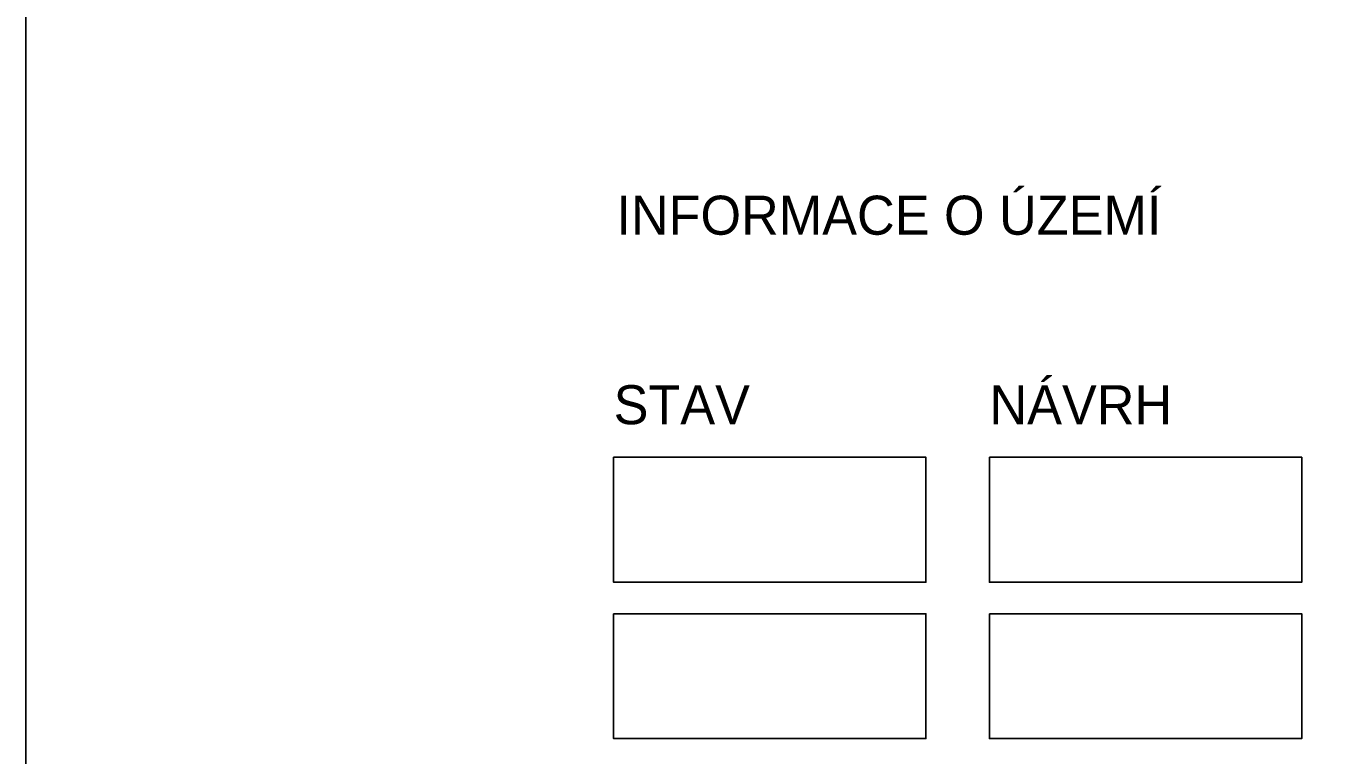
# Model space of a CAD drawing. Extents: x -449577 to -425530, y -1150048 to -1121091.
# Drawn here: x -443521.8 to -443089.1, y -1148794.2 to -1148551.4 of the extents above; entities that cross this region are included whole.
import ezdxf

# ---------------------------------------------------------------- set-up
doc = ezdxf.new("R2010")
doc.units = 0
doc.layers.add('Vrstva 1', color=7, linetype='Continuous')

msp = doc.modelspace()

# ---------------------------------------------------------------- linework, layer by layer
at = {"layer": 'Vrstva 1'}
for points in [[(-441021.77, -1148048.33), (-441021.77, -1150048.33), (-443521.77, -1150048.33), (-443521.77, -1148048.33)], [(-441021.77, -1148048.33), (-441021.77, -1150048.33), (-443521.77, -1150048.33), (-443521.77, -1148048.33)], [(-441021.77, -1148048.33), (-441021.77, -1150048.33), (-443521.77, -1150048.33), (-443521.77, -1148048.33)], [(-441021.77, -1148048.33), (-441021.77, -1150048.33), (-443521.77, -1150048.33), (-443521.77, -1148048.33)], [(-441021.77, -1148048.33), (-441021.77, -1150048.33), (-443521.77, -1150048.33), (-443521.77, -1148048.33)], [(-441021.77, -1148048.33), (-441021.77, -1150048.33), (-443521.77, -1150048.33), (-443521.77, -1148048.33)], [(-441021.77, -1148048.33), (-441021.77, -1150048.33), (-443521.77, -1150048.33), (-443521.77, -1148048.33)], [(-441021.77, -1148048.33), (-441021.77, -1150048.33), (-443521.77, -1150048.33), (-443521.77, -1148048.33)], [(-441021.77, -1148048.33), (-441021.77, -1150048.33), (-443521.77, -1150048.33), (-443521.77, -1148048.33)], [(-441021.77, -1148048.33), (-441021.77, -1150048.33), (-443521.77, -1150048.33), (-443521.77, -1148048.33)], [(-441021.77, -1148048.33), (-441021.77, -1150048.33), (-443521.77, -1150048.33), (-443521.77, -1148048.33)], [(-441021.77, -1148048.33), (-441021.77, -1150048.33), (-443521.77, -1150048.33), (-443521.77, -1148048.33)], [(-441021.77, -1148048.33), (-441021.77, -1150048.33), (-443521.77, -1150048.33), (-443521.77, -1148048.33)], [(-441021.77, -1148048.33), (-441021.77, -1150048.33), (-443521.77, -1150048.33), (-443521.77, -1148048.33)], [(-441021.77, -1148048.33), (-441021.77, -1150048.33), (-443521.77, -1150048.33), (-443521.77, -1148048.33)], [(-441021.77, -1148048.33), (-441021.77, -1150048.33), (-443521.77, -1150048.33), (-443521.77, -1148048.33)], [(-441021.77, -1148048.33), (-441021.77, -1150048.33), (-443521.77, -1150048.33), (-443521.77, -1148048.33)], [(-441021.77, -1148048.33), (-441021.77, -1150048.33), (-443521.77, -1150048.33), (-443521.77, -1148048.33)], [(-441021.77, -1148048.33), (-441021.77, -1150048.33), (-443521.77, -1150048.33), (-443521.77, -1148048.33)], [(-441021.77, -1148048.33), (-441021.77, -1150048.33), (-443521.77, -1150048.33), (-443521.77, -1148048.33)], [(-441021.77, -1148048.33), (-441021.77, -1150048.33), (-443521.77, -1150048.33), (-443521.77, -1148048.33)], [(-441021.77, -1148048.33), (-441021.77, -1150048.33), (-443521.77, -1150048.33), (-443521.77, -1148048.33)], [(-441021.77, -1148048.33), (-441021.77, -1150048.33), (-443521.77, -1150048.33), (-443521.77, -1148048.33)], [(-441021.77, -1148048.33), (-441021.77, -1150048.33), (-443521.77, -1150048.33), (-443521.77, -1148048.33)], [(-441021.77, -1148048.33), (-441021.77, -1150048.33), (-443521.77, -1150048.33), (-443521.77, -1148048.33)], [(-441021.77, -1148048.33), (-441021.77, -1150048.33), (-443521.77, -1150048.33), (-443521.77, -1148048.33)], [(-441021.77, -1148048.33), (-441021.77, -1150048.33), (-443521.77, -1150048.33), (-443521.77, -1148048.33)], [(-441021.77, -1148048.33), (-441021.77, -1150048.33), (-443521.77, -1150048.33), (-443521.77, -1148048.33)], [(-441021.77, -1148048.33), (-441021.77, -1150048.33), (-443521.77, -1150048.33), (-443521.77, -1148048.33)], [(-441021.77, -1148048.33), (-441021.77, -1150048.33), (-443521.77, -1150048.33), (-443521.77, -1148048.33)], [(-441021.77, -1148048.33), (-441021.77, -1150048.33), (-443521.77, -1150048.33), (-443521.77, -1148048.33)], [(-441021.77, -1148048.33), (-441021.77, -1150048.33), (-443521.77, -1150048.33), (-443521.77, -1148048.33)], [(-443326.02, -1148695.02), (-443222.02, -1148695.02), (-443222.02, -1148736.62), (-443326.02, -1148736.62)], [(-443326.02, -1148695.02), (-443222.02, -1148695.02), (-443222.02, -1148736.62), (-443326.02, -1148736.62)], [(-443326.02, -1148695.02), (-443222.02, -1148695.02), (-443222.02, -1148736.62), (-443326.02, -1148736.62)], [(-443326.02, -1148695.02), (-443222.02, -1148695.02), (-443222.02, -1148736.62), (-443326.02, -1148736.62)], [(-443326.02, -1148695.02), (-443222.02, -1148695.02), (-443222.02, -1148736.62), (-443326.02, -1148736.62)], [(-443326.02, -1148695.02), (-443222.02, -1148695.02), (-443222.02, -1148736.62), (-443326.02, -1148736.62)], [(-443326.02, -1148695.02), (-443222.02, -1148695.02), (-443222.02, -1148736.62), (-443326.02, -1148736.62)], [(-443326.02, -1148695.02), (-443222.02, -1148695.02), (-443222.02, -1148736.62), (-443326.02, -1148736.62)], [(-443326.02, -1148695.02), (-443222.02, -1148695.02), (-443222.02, -1148736.62), (-443326.02, -1148736.62)], [(-443326.02, -1148695.02), (-443222.02, -1148695.02), (-443222.02, -1148736.62), (-443326.02, -1148736.62)], [(-443326.02, -1148695.02), (-443222.02, -1148695.02), (-443222.02, -1148736.62), (-443326.02, -1148736.62)], [(-443326.02, -1148695.02), (-443222.02, -1148695.02), (-443222.02, -1148736.62), (-443326.02, -1148736.62)], [(-443326.02, -1148695.02), (-443222.02, -1148695.02), (-443222.02, -1148736.62), (-443326.02, -1148736.62)], [(-443326.02, -1148695.02), (-443222.02, -1148695.02), (-443222.02, -1148736.62), (-443326.02, -1148736.62)], [(-443326.02, -1148695.02), (-443222.02, -1148695.02), (-443222.02, -1148736.62), (-443326.02, -1148736.62)], [(-443326.02, -1148695.02), (-443222.02, -1148695.02), (-443222.02, -1148736.62), (-443326.02, -1148736.62)], [(-443326.02, -1148695.02), (-443222.02, -1148695.02), (-443222.02, -1148736.62), (-443326.02, -1148736.62)], [(-443326.02, -1148695.02), (-443222.02, -1148695.02), (-443222.02, -1148736.62), (-443326.02, -1148736.62)], [(-443326.02, -1148695.02), (-443222.02, -1148695.02), (-443222.02, -1148736.62), (-443326.02, -1148736.62)], [(-443326.02, -1148695.02), (-443222.02, -1148695.02), (-443222.02, -1148736.62), (-443326.02, -1148736.62)], [(-443326.02, -1148695.02), (-443222.02, -1148695.02), (-443222.02, -1148736.62), (-443326.02, -1148736.62)], [(-443326.02, -1148695.02), (-443222.02, -1148695.02), (-443222.02, -1148736.62), (-443326.02, -1148736.62)], [(-443326.02, -1148695.02), (-443222.02, -1148695.02), (-443222.02, -1148736.62), (-443326.02, -1148736.62)], [(-443326.02, -1148695.02), (-443222.02, -1148695.02), (-443222.02, -1148736.62), (-443326.02, -1148736.62)], [(-443326.02, -1148695.02), (-443222.02, -1148695.02), (-443222.02, -1148736.62), (-443326.02, -1148736.62)], [(-443326.02, -1148695.02), (-443222.02, -1148695.02), (-443222.02, -1148736.62), (-443326.02, -1148736.62)], [(-443326.02, -1148695.02), (-443222.02, -1148695.02), (-443222.02, -1148736.62), (-443326.02, -1148736.62)], [(-443326.02, -1148695.02), (-443222.02, -1148695.02), (-443222.02, -1148736.62), (-443326.02, -1148736.62)], [(-443326.02, -1148695.02), (-443222.02, -1148695.02), (-443222.02, -1148736.62), (-443326.02, -1148736.62)], [(-443326.02, -1148695.02), (-443222.02, -1148695.02), (-443222.02, -1148736.62), (-443326.02, -1148736.62)], [(-443326.02, -1148695.02), (-443222.02, -1148695.02), (-443222.02, -1148736.62), (-443326.02, -1148736.62)], [(-443326.02, -1148695.02), (-443222.02, -1148695.02), (-443222.02, -1148736.62), (-443326.02, -1148736.62)], [(-443200.82, -1148695.02), (-443096.82, -1148695.02), (-443096.82, -1148736.62), (-443200.82, -1148736.62)], [(-443200.82, -1148695.02), (-443096.82, -1148695.02), (-443096.82, -1148736.62), (-443200.82, -1148736.62)], [(-443200.82, -1148695.02), (-443096.82, -1148695.02), (-443096.82, -1148736.62), (-443200.82, -1148736.62)], [(-443200.82, -1148695.02), (-443096.82, -1148695.02), (-443096.82, -1148736.62), (-443200.82, -1148736.62)], [(-443200.82, -1148695.02), (-443096.82, -1148695.02), (-443096.82, -1148736.62), (-443200.82, -1148736.62)], [(-443200.82, -1148695.02), (-443096.82, -1148695.02), (-443096.82, -1148736.62), (-443200.82, -1148736.62)], [(-443200.82, -1148695.02), (-443096.82, -1148695.02), (-443096.82, -1148736.62), (-443200.82, -1148736.62)], [(-443200.82, -1148695.02), (-443096.82, -1148695.02), (-443096.82, -1148736.62), (-443200.82, -1148736.62)], [(-443200.82, -1148695.02), (-443096.82, -1148695.02), (-443096.82, -1148736.62), (-443200.82, -1148736.62)], [(-443200.82, -1148695.02), (-443096.82, -1148695.02), (-443096.82, -1148736.62), (-443200.82, -1148736.62)], [(-443200.82, -1148695.02), (-443096.82, -1148695.02), (-443096.82, -1148736.62), (-443200.82, -1148736.62)], [(-443200.82, -1148695.02), (-443096.82, -1148695.02), (-443096.82, -1148736.62), (-443200.82, -1148736.62)], [(-443200.82, -1148695.02), (-443096.82, -1148695.02), (-443096.82, -1148736.62), (-443200.82, -1148736.62)], [(-443200.82, -1148695.02), (-443096.82, -1148695.02), (-443096.82, -1148736.62), (-443200.82, -1148736.62)], [(-443200.82, -1148695.02), (-443096.82, -1148695.02), (-443096.82, -1148736.62), (-443200.82, -1148736.62)], [(-443200.82, -1148695.02), (-443096.82, -1148695.02), (-443096.82, -1148736.62), (-443200.82, -1148736.62)], [(-443200.82, -1148695.02), (-443096.82, -1148695.02), (-443096.82, -1148736.62), (-443200.82, -1148736.62)], [(-443200.82, -1148695.02), (-443096.82, -1148695.02), (-443096.82, -1148736.62), (-443200.82, -1148736.62)], [(-443200.82, -1148695.02), (-443096.82, -1148695.02), (-443096.82, -1148736.62), (-443200.82, -1148736.62)], [(-443200.82, -1148695.02), (-443096.82, -1148695.02), (-443096.82, -1148736.62), (-443200.82, -1148736.62)], [(-443200.82, -1148695.02), (-443096.82, -1148695.02), (-443096.82, -1148736.62), (-443200.82, -1148736.62)], [(-443200.82, -1148695.02), (-443096.82, -1148695.02), (-443096.82, -1148736.62), (-443200.82, -1148736.62)], [(-443200.82, -1148695.02), (-443096.82, -1148695.02), (-443096.82, -1148736.62), (-443200.82, -1148736.62)], [(-443200.82, -1148695.02), (-443096.82, -1148695.02), (-443096.82, -1148736.62), (-443200.82, -1148736.62)], [(-443200.82, -1148695.02), (-443096.82, -1148695.02), (-443096.82, -1148736.62), (-443200.82, -1148736.62)], [(-443200.82, -1148695.02), (-443096.82, -1148695.02), (-443096.82, -1148736.62), (-443200.82, -1148736.62)], [(-443200.82, -1148695.02), (-443096.82, -1148695.02), (-443096.82, -1148736.62), (-443200.82, -1148736.62)], [(-443200.82, -1148695.02), (-443096.82, -1148695.02), (-443096.82, -1148736.62), (-443200.82, -1148736.62)], [(-443200.82, -1148695.02), (-443096.82, -1148695.02), (-443096.82, -1148736.62), (-443200.82, -1148736.62)], [(-443200.82, -1148695.02), (-443096.82, -1148695.02), (-443096.82, -1148736.62), (-443200.82, -1148736.62)], [(-443200.82, -1148695.02), (-443096.82, -1148695.02), (-443096.82, -1148736.62), (-443200.82, -1148736.62)], [(-443200.82, -1148695.02), (-443096.82, -1148695.02), (-443096.82, -1148736.62), (-443200.82, -1148736.62)], [(-443326.02, -1148747.11), (-443222.02, -1148747.11), (-443222.02, -1148788.71), (-443326.02, -1148788.71)], [(-443326.02, -1148747.11), (-443222.02, -1148747.11), (-443222.02, -1148788.71), (-443326.02, -1148788.71)], [(-443326.02, -1148747.11), (-443222.02, -1148747.11), (-443222.02, -1148788.71), (-443326.02, -1148788.71)], [(-443326.02, -1148747.11), (-443222.02, -1148747.11), (-443222.02, -1148788.71), (-443326.02, -1148788.71)], [(-443326.02, -1148747.11), (-443222.02, -1148747.11), (-443222.02, -1148788.71), (-443326.02, -1148788.71)], [(-443326.02, -1148747.11), (-443222.02, -1148747.11), (-443222.02, -1148788.71), (-443326.02, -1148788.71)], [(-443326.02, -1148747.11), (-443222.02, -1148747.11), (-443222.02, -1148788.71), (-443326.02, -1148788.71)], [(-443326.02, -1148747.11), (-443222.02, -1148747.11), (-443222.02, -1148788.71), (-443326.02, -1148788.71)], [(-443326.02, -1148747.11), (-443222.02, -1148747.11), (-443222.02, -1148788.71), (-443326.02, -1148788.71)], [(-443326.02, -1148747.11), (-443222.02, -1148747.11), (-443222.02, -1148788.71), (-443326.02, -1148788.71)], [(-443326.02, -1148747.11), (-443222.02, -1148747.11), (-443222.02, -1148788.71), (-443326.02, -1148788.71)], [(-443326.02, -1148747.11), (-443222.02, -1148747.11), (-443222.02, -1148788.71), (-443326.02, -1148788.71)], [(-443326.02, -1148747.11), (-443222.02, -1148747.11), (-443222.02, -1148788.71), (-443326.02, -1148788.71)], [(-443326.02, -1148747.11), (-443222.02, -1148747.11), (-443222.02, -1148788.71), (-443326.02, -1148788.71)], [(-443326.02, -1148747.11), (-443222.02, -1148747.11), (-443222.02, -1148788.71), (-443326.02, -1148788.71)], [(-443326.02, -1148747.11), (-443222.02, -1148747.11), (-443222.02, -1148788.71), (-443326.02, -1148788.71)], [(-443200.82, -1148747.11), (-443096.82, -1148747.11), (-443096.82, -1148788.71), (-443200.82, -1148788.71)], [(-443200.82, -1148747.11), (-443096.82, -1148747.11), (-443096.82, -1148788.71), (-443200.82, -1148788.71)], [(-443200.82, -1148747.11), (-443096.82, -1148747.11), (-443096.82, -1148788.71), (-443200.82, -1148788.71)], [(-443200.82, -1148747.11), (-443096.82, -1148747.11), (-443096.82, -1148788.71), (-443200.82, -1148788.71)], [(-443200.82, -1148747.11), (-443096.82, -1148747.11), (-443096.82, -1148788.71), (-443200.82, -1148788.71)], [(-443200.82, -1148747.11), (-443096.82, -1148747.11), (-443096.82, -1148788.71), (-443200.82, -1148788.71)], [(-443200.82, -1148747.11), (-443096.82, -1148747.11), (-443096.82, -1148788.71), (-443200.82, -1148788.71)], [(-443200.82, -1148747.11), (-443096.82, -1148747.11), (-443096.82, -1148788.71), (-443200.82, -1148788.71)], [(-443200.82, -1148747.11), (-443096.82, -1148747.11), (-443096.82, -1148788.71), (-443200.82, -1148788.71)], [(-443200.82, -1148747.11), (-443096.82, -1148747.11), (-443096.82, -1148788.71), (-443200.82, -1148788.71)], [(-443200.82, -1148747.11), (-443096.82, -1148747.11), (-443096.82, -1148788.71), (-443200.82, -1148788.71)], [(-443200.82, -1148747.11), (-443096.82, -1148747.11), (-443096.82, -1148788.71), (-443200.82, -1148788.71)], [(-443200.82, -1148747.11), (-443096.82, -1148747.11), (-443096.82, -1148788.71), (-443200.82, -1148788.71)], [(-443200.82, -1148747.11), (-443096.82, -1148747.11), (-443096.82, -1148788.71), (-443200.82, -1148788.71)], [(-443200.82, -1148747.11), (-443096.82, -1148747.11), (-443096.82, -1148788.71), (-443200.82, -1148788.71)], [(-443200.82, -1148747.11), (-443096.82, -1148747.11), (-443096.82, -1148788.71), (-443200.82, -1148788.71)]]:
    msp.add_lwpolyline(points, close=True, dxfattribs=at)

# ---------------------------------------------------------------- texts
for s, height, p in [('INFORMACE O ÚZEMÍ', 12.9974, (-443325.09, -1148620.89)), ('INFORMACE O ÚZEMÍ', 12.9974, (-443325.09, -1148620.89)), ('INFORMACE O ÚZEMÍ', 12.9974, (-443325.09, -1148620.89)), ('INFORMACE O ÚZEMÍ', 12.9974, (-443325.09, -1148620.89)), ('INFORMACE O ÚZEMÍ', 12.9974, (-443325.09, -1148620.89)), ('INFORMACE O ÚZEMÍ', 12.9974, (-443325.09, -1148620.89)), ('INFORMACE O ÚZEMÍ', 12.9974, (-443325.09, -1148620.89)), ('INFORMACE O ÚZEMÍ', 12.9974, (-443325.09, -1148620.89)), ('NÁVRH', 12.997, (-443200.82, -1148684.01)), ('NÁVRH', 12.997, (-443200.82, -1148684.01)), ('NÁVRH', 12.997, (-443200.82, -1148684.01)), ('NÁVRH', 12.997, (-443200.82, -1148684.01)), ('NÁVRH', 12.997, (-443200.82, -1148684.01)), ('NÁVRH', 12.997, (-443200.82, -1148684.01)), ('NÁVRH', 12.997, (-443200.82, -1148684.01)), ('NÁVRH', 12.997, (-443200.82, -1148684.01)), ('NÁVRH', 12.997, (-443200.82, -1148684.01)), ('NÁVRH', 12.997, (-443200.82, -1148684.01)), ('NÁVRH', 12.997, (-443200.82, -1148684.01)), ('NÁVRH', 12.997, (-443200.82, -1148684.01)), ('NÁVRH', 12.997, (-443200.82, -1148684.01)), ('NÁVRH', 12.997, (-443200.82, -1148684.01)), ('NÁVRH', 12.997, (-443200.82, -1148684.01)), ('NÁVRH', 12.997, (-443200.82, -1148684.01)), ('STAV', 12.997, (-443326.02, -1148684.01)), ('STAV', 12.997, (-443326.02, -1148684.01)), ('STAV', 12.997, (-443326.02, -1148684.01)), ('STAV', 12.997, (-443326.02, -1148684.01)), ('STAV', 12.997, (-443326.02, -1148684.01)), ('STAV', 12.997, (-443326.02, -1148684.01)), ('STAV', 12.997, (-443326.02, -1148684.01)), ('STAV', 12.997, (-443326.02, -1148684.01)), ('STAV', 12.997, (-443326.02, -1148684.01)), ('STAV', 12.997, (-443326.02, -1148684.01)), ('STAV', 12.997, (-443326.02, -1148684.01)), ('STAV', 12.997, (-443326.02, -1148684.01)), ('STAV', 12.997, (-443326.02, -1148684.01)), ('STAV', 12.997, (-443326.02, -1148684.01)), ('STAV', 12.997, (-443326.02, -1148684.01)), ('STAV', 12.997, (-443326.02, -1148684.01))]:
    msp.add_text(s, height=height, dxfattribs=at).set_placement(p)

doc.saveas('drawing.dxf')
